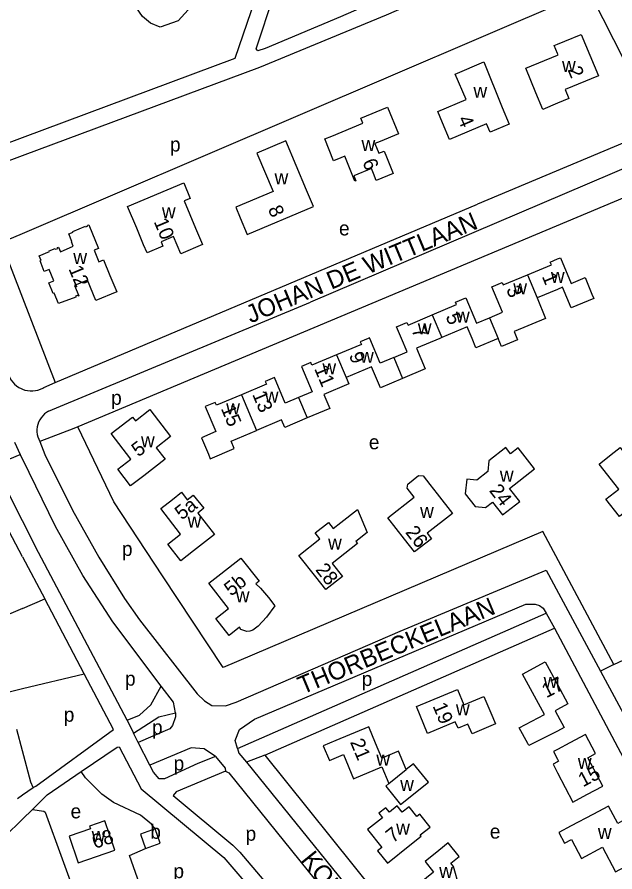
# Model space of a CAD drawing. Extents: x 162427 to 165104, y 384242 to 386287.
# Drawn here: x 163348.5 to 163516.1, y 384850.5 to 385090 of the extents above; entities that cross this region are included whole.
import ezdxf

# ---------------------------------------------------------------- set-up
doc = ezdxf.new("R2010")
doc.units = 0
for name, color, linetype in [('BLT_Basislijn', 7, 'Continuous'), ('BLT_Bebouwing', 7, 'Continuous'), ('BLT_Centroide', 7, 'Continuous'), ('BLT_Huisnummer', 7, 'Continuous'), ('BLT_Huisnummer_ tussenligend', 7, 'Continuous'), ('BLT_Onderverdeling_panden', 7, 'Continuous'), ('BLT_Straatnaam', 7, 'Continuous')]:
    doc.layers.add(name, color=color, linetype=linetype)

msp = doc.modelspace()

# ---------------------------------------------------------------- linework, layer by layer
at = {"layer": 'BLT_Basislijn'}
for p, q in [((163350, 385029.4), (163508.81, 385097.35)), ((163508.81, 385097.35), (163528.32, 385058.81)), ((163527.9, 385058.67), (163477.55, 385037.61)), ((163319.54, 385045), (163350, 385056.33)), ((163532.27, 385053.41), (163430.74, 385010.19)), ((163321.58, 385040.73), (163350, 385051.29)), ((163536.59, 385046.92), (163365.48, 384975.25)), ((163359.21, 384987.6), (163477.55, 385037.61)), ((163343.98, 385026.83), (163350, 385029.4)), ((163343.98, 385026.83), (163350, 385011.33)), ((163350, 385011.33), (163359.21, 384987.6)), ((163357.31, 384979.63), (163430.74, 385010.19)), ((163355.99, 384986.23), (163359.21, 384987.6)), ((163365.48, 384975.25), (163364.4, 384974.8)), ((163364.4, 384974.8), (163354.88, 384971.08)), ((163347.73, 384970.96), (163349.38, 384967.49)), ((163350, 384966.23), (163349.38, 384967.49)), ((163515.79, 384908.62), (163495.92, 384945.93)), ((163350, 384938.77), (163356.24, 384927.01)), ((163496.87, 384935.11), (163500.32, 384928.6)), ((163350, 384924.36), (163356.24, 384927.01)), ((163367.28, 384906.03), (163356.24, 384927.01)), ((163410.31, 384885.06), (163496.8, 384922.99)), ((163496.8, 384922.99), (163499.13, 384918.85)), ((163417.99, 384883.24), (163499.13, 384918.85)), ((163515.79, 384908.62), (163512.07, 384906.8)), ((163350, 384901.91), (163367.28, 384906.03)), ((163345.88, 384900.92), (163350, 384901.91)), ((163379.36, 384893.08), (163381.17, 384889.41)), ((163350, 384884.47), (163348.41, 384890.46)), ((163382.48, 384886.8), (163381.17, 384889.41)), ((163385.7, 384880.47), (163382.48, 384886.8)), ((163417.99, 384883.24), (163412.77, 384881.27)), ((163417.99, 384883.24), (163514.84, 384762.64)), ((163348.56, 384871.06), (163350, 384872.09)), ((163350, 384872.09), (163352.97, 384874.22)), ((163350, 384865.28), (163352.83, 384868.05))]:
    msp.add_line(p, q, dxfattribs=at)
for points in [[(163350, 385056.33), (163409.61, 385078.5), (163424.16, 385120.85), (163427.49, 385129.82), (163469.14, 385163.28)], [(163499.03, 385116.67), (163486.56, 385110.82), (163439.18, 385090.14), (163418, 385081.25), (163415.95, 385080.57), (163415.49, 385081.11), (163430.4, 385126.04), (163472.35, 385159.4)], [(163350, 385051.29), (163416.51, 385076.02), (163452.08, 385090.68), (163501.35, 385112.08)], [(163346.18, 384989.63), (163346.48, 384988.96), (163346.85, 384988.32), (163347.29, 384987.73), (163347.79, 384987.19), (163348.35, 384986.71), (163348.95, 384986.29), (163349.6, 384985.93), (163350, 384985.76)], [(163350, 384985.76), (163350.7, 384985.52), (163351.42, 384985.36), (163352.15, 384985.28), (163352.88, 384985.28), (163353.62, 384985.36), (163354.33, 384985.52), (163355.03, 384985.76), (163355.7, 384986.07), (163355.99, 384986.23)], [(163357.31, 384979.63), (163356.71, 384979.26), (163356.16, 384978.83), (163355.66, 384978.33), (163355.22, 384977.78), (163354.84, 384977.18), (163354.53, 384976.55), (163354.3, 384975.88), (163354.15, 384975.2), (163354.07, 384974.49), (163354.07, 384973.79), (163354.15, 384973.09), (163354.32, 384972.4), (163354.55, 384971.74), (163354.88, 384971.08)], [(163495.92, 384945.93), (163406.26, 384907.76), (163389.25, 384933.46), (163375.64, 384954.25), (163365.48, 384975.25)], [(163354.88, 384971.08), (163356.27, 384967.49), (163364, 384951.86), (163371.43, 384938.75), (163378.65, 384927.12), (163382.79, 384921.16), (163399.01, 384900.41), (163400.99, 384898.45), (163403.08, 384897.18), (163406.96, 384897.04), (163409.92, 384898.12), (163455.89, 384917.95), (163496.87, 384935.11)], [(163350, 384948.87), (163342.53, 384963.47), (163342.38, 384964.54), (163349.38, 384967.49)], [(163388.91, 384902.54), (163375.31, 384920.62), (163366.88, 384933.58), (163359.23, 384947.34), (163350, 384966.23)], [(163350, 384938.77), (163337.83, 384961.72), (163337.03, 384962.14), (163336.25, 384962.03), (163302.47, 384948.03), (163279.02, 384938.27), (163179.71, 384895.48)], [(163379.36, 384893.08), (163354.51, 384940.05), (163350, 384948.87)], [(163500.32, 384928.6), (163512.07, 384906.8)], [(163410.31, 384885.06), (163409.67, 384887.35), (163410.83, 384890.39), (163415.02, 384893.29), (163491.12, 384925.56), (163493.78, 384925.52), (163494.94, 384925.15), (163495.99, 384924.45), (163496.8, 384922.99)], [(163350, 384924.36), (163302.31, 384904.04), (163247.18, 384880.45)], [(163499.13, 384918.85), (163551.47, 384820.31), (163567.94, 384789.85)], [(163515.79, 384908.62), (163518.62, 384909.99), (163519.44, 384908.92), (163579.41, 384796.34), (163580.59, 384796.32), (163583.77, 384797.88), (163647.49, 384830.54)], [(163352.97, 384874.22), (163353.76, 384874.55), (163375.51, 384890.47), (163367.28, 384906.03)], [(163512.07, 384906.8), (163564.56, 384809.44), (163575.38, 384788.87)], [(163379.36, 384893.08), (163382.79, 384894.45), (163386.02, 384897.33), (163388.91, 384902.54)], [(163392.88, 384895.12), (163392.33, 384898.1), (163388.91, 384902.54)], [(163381.17, 384889.41), (163388.26, 384894), (163392.88, 384895.12)], [(163392.88, 384895.12), (163392.91, 384893.95), (163392.02, 384891.56), (163391.32, 384890.6), (163382.48, 384886.8)], [(163352.97, 384874.22), (163352.32, 384875.71), (163350, 384884.47)], [(163366.48, 384878.63), (163376.58, 384885.47), (163377.15, 384885.54), (163383.26, 384873.76), (163406.49, 384854.58), (163436.33, 384819.73), (163439.79, 384819.92), (163447.58, 384812.71)], [(163404.13, 384882.82), (163400.98, 384885.02), (163397.26, 384885.3), (163385.7, 384880.47)], [(163410.31, 384885.06), (163410.69, 384883.77), (163412.77, 384881.27)], [(163404.13, 384882.82), (163399.21, 384880.92), (163389.86, 384876.58), (163388.35, 384876.58), (163386.76, 384878.46), (163385.7, 384880.47)], [(163404.13, 384882.82), (163406.8, 384879.59), (163406.91, 384878.75)], [(163412.77, 384881.27), (163509.26, 384762.09), (163511.01, 384760.54)], [(163352.83, 384868.05), (163356.92, 384872.11), (163366.48, 384878.63)], [(163387.23, 384862.56), (163386.13, 384863.9), (163383.1, 384866.38), (163375.56, 384870), (163372.29, 384872.28), (163367.65, 384876.9), (163366.48, 384878.63)], [(163406.91, 384878.75), (163393.06, 384872.97), (163392.27, 384871.95), (163408.94, 384858.03), (163410.92, 384856.05), (163437.89, 384824.35), (163440.6, 384824.48), (163441.54, 384824.24), (163450.57, 384816.07), (163495.55, 384761.86), (163497.96, 384759.38), (163501.4, 384760.97)], [(163406.91, 384878.75), (163407.84, 384878.3), (163498.38, 384766.08), (163501.3, 384762.25), (163501.4, 384760.97)], [(163352.83, 384868.05), (163356.01, 384867.59), (163356.33, 384867.27), (163365.92, 384841.15), (163378.06, 384845.27), (163382.79, 384847.15), (163379.99, 384855.09), (163384.47, 384857.07)], [(163343.71, 384838.57), (163331.24, 384833.13), (163330.27, 384833.17), (163328.11, 384839.59), (163328.42, 384843.51), (163330.13, 384845.86), (163350, 384865.28)]]:
    msp.add_lwpolyline(points, dxfattribs=at)
msp.add_lwpolyline([(163399.12, 385095.13), (163393.66, 385088.98), (163388.59, 385087.24), (163385.87, 385088.32), (163383.62, 385090.18), (163381.98, 385092.59), (163381.19, 385095.4), (163381.27, 385098.32), (163382.36, 385101.33), (163384.89, 385104.76), (163388.28, 385108.14), (163391.88, 385110.63), (163395.51, 385112.39), (163398.86, 385113.52), (163401.83, 385113.47), (163404.65, 385112.53), (163406.88, 385111.1), (163408.72, 385109.21), (163409.97, 385106.88), (163410.54, 385104.99), (163409.65, 385099.84)], close=True, dxfattribs=at)
at = {"layer": 'BLT_Bebouwing'}
for points in [[(163500, 385079.4), (163500.16, 385079.46), (163500, 385079.84), (163499.09, 385082.03), (163500, 385082.41), (163502.05, 385083.26), (163506.66, 385085.17), (163511.47, 385073.59), (163502.16, 385069.72), (163503.2, 385067.21), (163500, 385065.88), (163495.88, 385064.17), (163493.97, 385068.79), (163491.1, 385075.7), (163500, 385079.4)], [(163484.49, 385064.65), (163486.43, 385060.04), (163481.09, 385057.79), (163480.1, 385060.14), (163469.73, 385055.77), (163467.78, 385060.38), (163466.45, 385063.55), (163474.39, 385066.9), (163471.36, 385074.07), (163479.35, 385077.44), (163484.49, 385064.65)], [(163436.71, 385056.69), (163445.42, 385060.26), (163444.84, 385061.67), (163452.33, 385064.75), (163455.39, 385057.29), (163450.26, 385055.19), (163448.83, 385054.6), (163449.95, 385051.87), (163451.38, 385052.46), (163452.05, 385050.85)], [(163439.22, 385050.57), (163437.25, 385049.76), (163434.74, 385055.88), (163436.71, 385056.69)], [(163429.62, 385041.56), (163423.83, 385055.34), (163415.74, 385051.93), (163420.26, 385041.19), (163409.78, 385036.79), (163411.06, 385033.76), (163412.99, 385029.15), (163431.56, 385036.95), (163429.62, 385041.56)], [(163452.05, 385050.85), (163453.94, 385046.22), (163449.21, 385044.28), (163448.43, 385046.2), (163447.87, 385047.56), (163442.94, 385045.54), (163443.5, 385044.17), (163443.2, 385044.05), (163441.3, 385048.68), (163440.34, 385051.03), (163439.22, 385050.57)], [(163384.93, 385023.94), (163383.96, 385026.25), (163382.02, 385030.86), (163379.46, 385036.94), (163395.21, 385043.57), (163397.03, 385039.23), (163395.29, 385038.5), (163398.5, 385030.88), (163400.44, 385026.27), (163394.42, 385023.74), (163392.38, 385028.59), (163388.85, 385027.1)], [(163367.66, 385031.48), (163367.74, 385031.3), (163368.35, 385031.55), (163368.27, 385031.74), (163368.56, 385031.86), (163371.34, 385025.22), (163370.1, 385024.69), (163371.45, 385021.47), (163372.69, 385021.99), (163374.51, 385017.65), (163376.44, 385013.04), (163370.58, 385010.58), (163368.21, 385016.28), (163364.62, 385014.81), (163365.82, 385011.92), (163365.53, 385011.8), (163365.43, 385012.06), (163364.82, 385011.79), (163364.92, 385011.54), (163360.1, 385009.75), (163358.92, 385012.7), (163358.62, 385012.58), (163357.43, 385015.53), (163358.82, 385016.09), (163357.52, 385019.34), (163356.12, 385018.78), (163354.94, 385021.73), (163355.23, 385021.85), (163354.72, 385023.13), (163357.55, 385024.32), (163357.48, 385024.5), (163359.19, 385025.22), (163359.3, 385024.96), (163359.91, 385025.21), (163359.8, 385025.47), (163360.09, 385025.59), (163360.63, 385024.3), (163364.24, 385025.81), (163363.7, 385027.1), (163363.88, 385027.18), (163362.99, 385029.31), (163364.19, 385029.81), (163364.11, 385029.99), (163367.66, 385031.48)], [(163388.85, 385027.1), (163389.39, 385025.81), (163384.93, 385023.94)], [(163491.56, 385017.81), (163498.3, 385020.65), (163497.98, 385021.4), (163500, 385022.25), (163500.83, 385022.6), (163503.87, 385015.39), (163507.73, 385017.02), (163509.67, 385012.41), (163510.18, 385011.2), (163503.85, 385008.53), (163501.42, 385014.32), (163500, 385013.73), (163494.29, 385011.32)], [(163480.91, 385005.8), (163484.55, 385007.34), (163481.56, 385014.44), (163484.51, 385015.68), (163484.81, 385014.97), (163491.56, 385017.81)], [(163464.91, 385006.61), (163471.72, 385009.48), (163471.42, 385010.18), (163474.27, 385011.39), (163477.27, 385004.27), (163480.91, 385005.8)], [(163494.29, 385011.32), (163496.69, 385005.61), (163487.86, 385001.89), (163488.83, 384999.58), (163484.34, 384997.69), (163483.36, 385000)], [(163454.09, 384994.66), (163457.85, 384996.24), (163456.27, 385000), (163454.89, 385003.28), (163457.78, 385004.5), (163458.1, 385003.74), (163464.91, 385006.61)], [(163483.36, 385000), (163477.15, 384997.38), (163476.04, 385000), (163474.68, 385003.23), (163467.59, 385000.24)], [(163454.09, 384994.66), (163450.32, 384993.07), (163447.41, 385000), (163447.34, 385000.16), (163446.95, 385000), (163444.7, 384999.05), (163445.02, 384998.31), (163438.08, 384995.39)], [(163467.59, 385000.24), (163467.03, 385000), (163460.49, 384997.25), (163462.93, 384991.46), (163456.56, 384988.78)], [(163438.08, 384995.39), (163431.15, 384992.47), (163430.82, 384993.26), (163428.21, 384992.17), (163431.2, 384985.06), (163427.42, 384983.47)], [(163456.56, 384988.78), (163450.34, 384986.15), (163447.87, 384992.02), (163440.77, 384989.03)], [(163427.42, 384983.47), (163423.63, 384981.87), (163420.62, 384989.02), (163418.08, 384987.95), (163418.41, 384987.18), (163411.4, 384984.23)], [(163440.77, 384989.03), (163441.52, 384987.23), (163434.5, 384984.28), (163436.15, 384980.36), (163429.84, 384977.71)], [(163411.4, 384984.23), (163404.39, 384981.28), (163404.06, 384982.07), (163401.26, 384980.89), (163404.22, 384973.88), (163400.18, 384972.17), (163402.12, 384967.57), (163402.65, 384966.3), (163409.38, 384969.14), (163408.51, 384971.19), (163415.63, 384974.19)], [(163391.54, 384972.56), (163387.46, 384969.38), (163389.97, 384966.15), (163383.99, 384961.54), (163380.32, 384958.7), (163376.72, 384963.34), (163380.41, 384966.2), (163374.9, 384973.33), (163380.88, 384977.94), (163381.67, 384976.9), (163385.71, 384980.04), (163391.54, 384972.56)], [(163429.84, 384977.71), (163423.55, 384975.06), (163422.66, 384977.16), (163415.63, 384974.19)], [(163515.03, 384967.43), (163517.57, 384969.42), (163518.37, 384968.4), (163521.99, 384971.25), (163527.84, 384963.8), (163524.19, 384961)], [(163477.39, 384960.25), (163474.61, 384960.57), (163474.14, 384956.46), (163476.91, 384952.94), (163479.86, 384952.59), (163481.83, 384954.13), (163484.62, 384950.57), (163489.43, 384954.34), (163486.59, 384957.97), (163493.56, 384963.44), (163490.91, 384966.82), (163488.95, 384969.32), (163486.84, 384967.67), (163485.5, 384969.39), (163480.75, 384965.66), (163480.5, 384962.68), (163477.39, 384960.25)], [(163524.19, 384961), (163526.69, 384957.82), (163527.05, 384958.1), (163527.23, 384957.87), (163526.87, 384957.59), (163520.88, 384952.87), (163517.38, 384950.12), (163513.6, 384954.93), (163517.23, 384957.78), (163511.7, 384964.81), (163515.03, 384967.43)], [(163466.24, 384956.48), (163470.53, 384950.98), (163463.47, 384945.46), (163464.7, 384943.89), (163459.93, 384940.16), (163457.13, 384943.74), (163452.45, 384949.74), (163459.84, 384955.52), (163457.89, 384958.02), (163458.02, 384959.2), (163461.06, 384961.57), (163462.35, 384961.46), (163464.24, 384959.03), (163466.24, 384956.48)], [(163392.06, 384954.9), (163394.59, 384956.89), (163396.21, 384954.81), (163397.89, 384956.12), (163400.81, 384952.4), (163399.12, 384951.08), (163403.82, 384945.07), (163397.94, 384940.47), (163394.38, 384937.67), (163390.72, 384942.34), (163394.34, 384945.17), (163388.75, 384952.31), (163392.06, 384954.9)], [(163443.89, 384952.09), (163446.62, 384945.64), (163443.45, 384943.14), (163443.91, 384942.56), (163436.84, 384936.97), (163439.73, 384933.32), (163435.04, 384929.61), (163432.23, 384933.17), (163427.49, 384939.16), (163433.37, 384943.82), (163432.04, 384945.5), (163435.76, 384948.44), (163437.12, 384946.73), (163439.27, 384948.43), (163443.89, 384952.09)], [(163405.62, 384934.06), (163411.24, 384938.47), (163416.34, 384931.99), (163415.41, 384931.26), (163416.77, 384930.01), (163418.99, 384927.37), (163420.75, 384925.11), (163418.42, 384921.88), (163416.11, 384919.38), (163414.62, 384918.25), (163413.78, 384917.98), (163412.9, 384917.91), (163412.02, 384918.12), (163411.25, 384918.47), (163410.81, 384919.07), (163407.91, 384916.79), (163404.21, 384921.49), (163407.8, 384924.32), (163402.24, 384931.4), (163405.62, 384934.06)], [(163500, 384903.03), (163502.94, 384897.6), (163500, 384896.01), (163499.33, 384895.65), (163500, 384894.42), (163501.85, 384890.99), (163500, 384889.99), (163497.42, 384888.68), (163491.97, 384885.92), (163491.68, 384886.46), (163489.3, 384890.85), (163496.34, 384894.67), (163490.23, 384905.95), (163496.56, 384909.38), (163500, 384903.03)], [(163473.76, 384897.34), (163479.37, 384899.69), (163481.3, 384895.08), (163482.6, 384891.98), (163476.07, 384889.23), (163474.89, 384891.93), (163472.17, 384890.78), (163471.34, 384892.57), (163463.59, 384889.33), (163460.45, 384896.85), (163471.96, 384901.67), (163473.76, 384897.34)], [(163457.61, 384879.22), (163455.41, 384884.38), (163450.74, 384882.42), (163449, 384886.58), (163447.07, 384891.19), (163437.89, 384887.36), (163434.34, 384885.87), (163436.06, 384881.77), (163440, 384883.41)], [(163508.27, 384872.19), (163512.69, 384874.53), (163508.47, 384882.52), (163510.69, 384883.69), (163507.88, 384889), (163503.46, 384886.67), (163500, 384884.84), (163498.87, 384884.24), (163500, 384882.1), (163500.31, 384881.52), (163500, 384881.36), (163498.75, 384880.7), (163500, 384878.33), (163504.34, 384870.11), (163508.27, 384872.19)], [(163440, 384883.41), (163442.83, 384876.65), (163443, 384876.72), (163450.76, 384879.96), (163452.71, 384875.29)], [(163452.71, 384875.29), (163451.87, 384874.58), (163455.99, 384869.43), (163463.8, 384875.68), (163459.67, 384880.83), (163457.61, 384879.22)], [(163458.64, 384858.01), (163461.81, 384860.54), (163461.54, 384860.88), (163464.28, 384863.07), (163461.39, 384866.69), (163460.6, 384866.05), (163458.4, 384868.79), (163456.45, 384867.23), (163455.04, 384869), (163452.86, 384867.26), (163451.87, 384868.49), (163449.93, 384866.94), (163450.91, 384865.72), (163446.75, 384862.37), (163450.74, 384857.39), (163449.54, 384856.43), (163452.33, 384852.95), (163458.64, 384858.01)], [(163517.48, 384851.18), (163521.89, 384853.52), (163521.55, 384854.16), (163524.34, 384855.64), (163522.46, 384859.17), (163521.82, 384858.83), (163519.41, 384863.37), (163521.11, 384864.28), (163520.24, 384865.92), (163516.89, 384864.13), (163514.33, 384868.97), (163509.91, 384866.62), (163503.89, 384863.42)], [(163363.11, 384860.5), (163365.65, 384853.09), (163375.94, 384856.61), (163373.13, 384864.82), (163368.8, 384863.34), (163369.07, 384862.55), (163363.11, 384860.5)], [(163387.23, 384862.56), (163383.05, 384861.07), (163384.47, 384857.07)], [(163384.47, 384857.07), (163388.65, 384858.56), (163387.23, 384862.56)], [(163503.89, 384863.42), (163500.38, 384861.55), (163501.94, 384858.6), (163503.9, 384859.65), (163506.73, 384854.32), (163512.62, 384857.45)], [(163471.76, 384842.97), (163473.86, 384844.66), (163472.46, 384846.41), (163470.84, 384852.02), (163470.09, 384852.95), (163472.43, 384854.85), (163469.38, 384858.64), (163466.77, 384856.55), (163462.87, 384853.42), (163465.26, 384850.45), (163459.81, 384846.08), (163464.03, 384840.81), (163466, 384838.35), (163471.76, 384842.97)], [(163512.62, 384857.45), (163516.29, 384850.55), (163517.48, 384851.18)]]:
    msp.add_lwpolyline(points, dxfattribs=at)
at = {"layer": 'BLT_Onderverdeling_panden'}
for p, q in [((163491.56, 385017.81), (163494.29, 385011.32)), ((163464.91, 385006.61), (163467.59, 385000.24)), ((163480.91, 385005.8), (163483.36, 385000)), ((163438.08, 384995.39), (163440.77, 384989.03)), ((163454.09, 384994.66), (163456.56, 384988.78)), ((163411.4, 384984.23), (163415.63, 384974.19)), ((163427.42, 384983.47), (163429.84, 384977.71)), ((163452.71, 384875.29), (163457.61, 384879.22))]:
    msp.add_line(p, q, dxfattribs=at)

# ---------------------------------------------------------------- texts
at = {"layer": 'BLT_Centroide'}
for s, p in [('w', (163501.27, 385074.66)), ('w', (163476.44, 385067.41)), ('p', (163391.35, 385052.37)), ('w', (163445.06, 385052.47)), ('w', (163420.67, 385043.19)), ('w', (163389.09, 385033.66)), ('e', (163438.75, 385028.85)), ('w', (163364.25, 385020.81)), ('w', (163498.15, 385015.56)), ('w', (163487.61, 385012.33)), ('w', (163471.53, 385004.38)), ('w', (163460.84, 385001.16)), ('w', (163444.66, 384993.16)), ('w', (163434.09, 384989.97)), ('w', (163417.95, 384982.03)), ('p', (163374.86, 384981.39)), ('w', (163407.12, 384978.72)), ('w', (163383.22, 384969.52)), ('e', (163447.12, 384968.94)), ('w', (163483.84, 384959.83)), ('w', (163461.48, 384949.7)), ('w', (163396.28, 384947.02)), ('w', (163435.68, 384940.84)), ('p', (163377.88, 384939.06)), ('w', (163409.81, 384926.09)), ('p', (163378.74, 384902.7)), ('p', (163445.12, 384902.62)), ('w', (163496.12, 384902.09)), ('w', (163471.53, 384894.41)), ('p', (163361.58, 384892.6)), ('p', (163386.31, 384889.06)), ('p', (163392.37, 384878.96)), ('w', (163449.22, 384880.31)), ('w', (163505.72, 384879.34)), ('w', (163455.89, 384873.22)), ('e', (163363.49, 384865.53)), ('b', (163385.84, 384859.81)), ('w', (163454.77, 384860.97)), ('e', (163481.04, 384859.86)), ('w', (163511.33, 384859.75)), ('w', (163369.39, 384858.94)), ('p', (163412.55, 384859.26)), ('p', (163392.33, 384848.78)), ('w', (163466.83, 384848.84))]:
    msp.add_text(s, height=4, dxfattribs=at).set_placement(p)
at = {"layer": 'BLT_Huisnummer'}
for s, rotation, p in [('2', 292.5263, (163502.78, 385075.31)), ('4', 292.8631, (163471.97, 385061.47)), ('6', 292.3184, (163445.23, 385049.44)), ('8', 292.8074, (163418.75, 385036.29)), ('10', 292.8375, (163386.74, 385032.74)), ('12', 292.5162, (163362.84, 385019.52)), ('1', 292.843, (163495.56, 385017.38)), ('5', 292.8425, (163468.57, 385006.17)), ('9', 292.8463, (163441.47, 384995.27)), ('15', 292.8406, (163405.56, 384980.39)), ('5', 37.7381, (163382.51, 384966.64)), ('24', 308.0839, (163480.7, 384957.3)), ('5a', 38.0862, (163394.67, 384948.96)), ('26', 307.9984, (163457.18, 384945.64)), ('28', 308.3342, (163431.98, 384935.13)), ('5b', 38.1853, (163408.5, 384927.61)), ('17', 26.8839, (163496.87, 384899.16)), ('19', 292.7204, (163464.93, 384897.04)), ('21', 292.6836, (163441.8, 384886.91)), ('15', 27.8568, (163507.15, 384874.2)), ('7', 38.6841, (163453.87, 384858.48)), ('68', 18.8995, (163370.29, 384856.93))]:
    msp.add_text(s, height=4, rotation=rotation, dxfattribs=at).set_placement(p)
at = {"layer": 'BLT_Huisnummer_ tussenligend'}
for s, rotation, p in [('3', 292.843, (163485.56, 385013.78)), ('7', 292.8425, (163458.96, 385002.38)), ('11', 292.8463, (163431.74, 384991.53)), ('13', 292.8463, (163414.36, 384984.34))]:
    msp.add_text(s, height=4, rotation=rotation, dxfattribs=at).set_placement(p)
at = {"layer": 'BLT_Straatnaam'}
for s, rotation, p in [('JOHAN DE WITTLAAN', 22.6558, (163413.95, 385004.16)), ('THORBECKELAAN', 22.6949, (163428.51, 384900.2)), ('KOUDENHOVENSEWEG NOORD', 308.9625, (163427.9, 384853.84))]:
    msp.add_text(s, height=5, rotation=rotation, dxfattribs=at).set_placement(p)

doc.saveas('drawing.dxf')
